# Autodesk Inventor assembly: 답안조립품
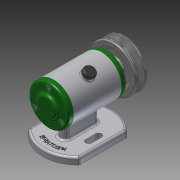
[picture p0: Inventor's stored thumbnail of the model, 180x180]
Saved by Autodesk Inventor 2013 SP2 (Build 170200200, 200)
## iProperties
Created: 2022-02
Part Number: 답안조립품
Document SubType Name: Assembly
Designer: i
Author: i
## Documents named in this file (14)
- C:\Users\i\Desktop\답안조립품.iam
- C:\Users\i\Desktop\본체.ipt
- C:\Users\i\Desktop\V벨트풀리.ipt
- C:\Users\i\Desktop\고무 캡.ipt
- C:\Users\i\Desktop\너트 M8.ipt
- C:\Users\i\Desktop\뒤커버.ipt
- C:\Users\i\Desktop\베어링 6002.ipt
- C:\Users\i\Desktop\볼트 M4 x 10.ipt
- C:\Users\i\Desktop\스프링와셔 8.ipt
- C:\Users\i\Desktop\앞커버.ipt
- C:\Users\i\Desktop\오일 실 15 x 25 x 7.ipt
- C:\Users\i\Desktop\축.ipt
- C:\Users\i\Desktop\키 3 x 3 x 12.ipt
- C:\Users\i\Desktop\평와셔 8 x 17.ipt
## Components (2 placed, 2 different names)
1. V벨트풀리:1
2. 고무 캡:1
